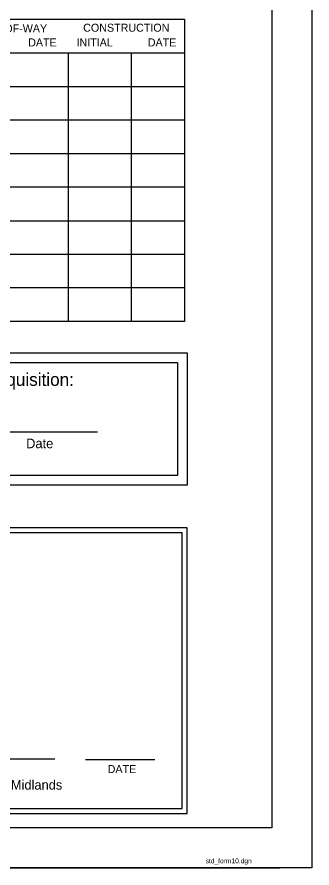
# Model space of a CAD drawing. Extents: x -796 to 2793, y -4650 to 4425.
# Drawn here: x 2596 to 2780, y 1000 to 1532 of the extents above; entities that cross this region are included whole.
import ezdxf

# ---------------------------------------------------------------- set-up
doc = ezdxf.new("R2010")
doc.units = 0
for name, color, linetype in [('RD_HC_CL', 7, 'Continuous'), ('RD_HC_Data', 7, 'Continuous'), ('RD_HC_Data_Tic', 7, 'Continuous'), ('RD_SHT_Bndy', 7, 'Continuous')]:
    doc.layers.add(name, color=color, linetype=linetype)

msp = doc.modelspace()

# ---------------------------------------------------------------- linework, layer by layer
at = {"layer": 'RD_HC_CL'}
msp.add_lwpolyline([(984.13, 2100), (2780.13, 2100), (2780.13, 1000), (984.13, 1000)], close=True, dxfattribs=at)
at = {"layer": 'RD_HC_Data'}
for p, q in [((2555.5, 1530.23), (2700.45, 1530.23)), ((2700.45, 1530.23), (2700.45, 1341.28)), ((2385.55, 1509.23), (2700.45, 1509.23)), ((2627.95, 1509.23), (2627.95, 1341.28)), ((2667.3, 1509.23), (2667.3, 1341.28)), ((2385.55, 1488.23), (2700.45, 1488.23)), ((2385.55, 1467.23), (2700.45, 1467.23)), ((2385.55, 1446.23), (2700.45, 1446.23)), ((2700.45, 1446.23), (2700.45, 1425.23)), ((2700.45, 1425.23), (2385.55, 1425.23)), ((2385.55, 1404.23), (2700.45, 1404.23)), ((2700.45, 1404.23), (2700.45, 1383.28)), ((2700.45, 1383.28), (2385.55, 1383.28)), ((2700.45, 1362.28), (2385.55, 1362.28)), ((2700.45, 1341.28), (2385.55, 1341.28)), ((2572.08, 1272.52), (2646.22, 1272.52)), ((2480.88, 1068.27), (2619.52, 1068.27)), ((2638.63, 1067.71), (2682.1, 1067.71)), ((2760, 1000), (1000, 1000)), ((1000, 1000), (2759.98, 1000))]:
    msp.add_line(p, q, dxfattribs=at)
for points in [[(1079.63, 2075.05), (2755.13, 2075.05), (2755.13, 1025), (1079.63, 1025)], [(2383.87, 1321.76), (2702.13, 1321.76), (2702.13, 1239.11), (2383.87, 1239.11)], [(2389.87, 1315.76), (2696.13, 1315.76), (2696.13, 1245.11), (2389.87, 1245.11)], [(2383.87, 1034.06), (2702.13, 1034.06), (2702.13, 1212.42), (2383.87, 1212.42)], [(2386.87, 1037.06), (2699.13, 1037.06), (2699.13, 1209.42), (2386.87, 1209.42)]]:
    msp.add_lwpolyline(points, close=True, dxfattribs=at)

# ---------------------------------------------------------------- texts
at = {"layer": 'RD_HC_Data_Tic'}
for s, p in [('RIGHT-OF-WAY', (2565.01, 1521.9)), ('CONSTRUCTION', (2637.27, 1522.35)), ('DATE', (2602.92, 1513.15)), ('INITIAL', (2633.12, 1513.15)), ('DATE', (2677.62, 1513.15))]:
    msp.add_text(s, height=4.998, rotation=360, dxfattribs=at).set_placement(p)
for s, height, p in [('Approved for Right Of Way Acquisition:', 8, (2445.98, 1301.11)), ('Date', 6, (2601.65, 1262.18)), ('DATE', 5, (2652.56, 1059.29)), ('std_form10.dgn', 3, (2713.75, 1002.95))]:
    msp.add_text(s, height=height, dxfattribs=at).set_placement(p)
at = {"layer": 'RD_SHT_Bndy'}
msp.add_text('Regional Production Engineer - Midlands', height=6, dxfattribs=at).set_placement((2478.37, 1048.92))

doc.saveas('drawing.dxf')
